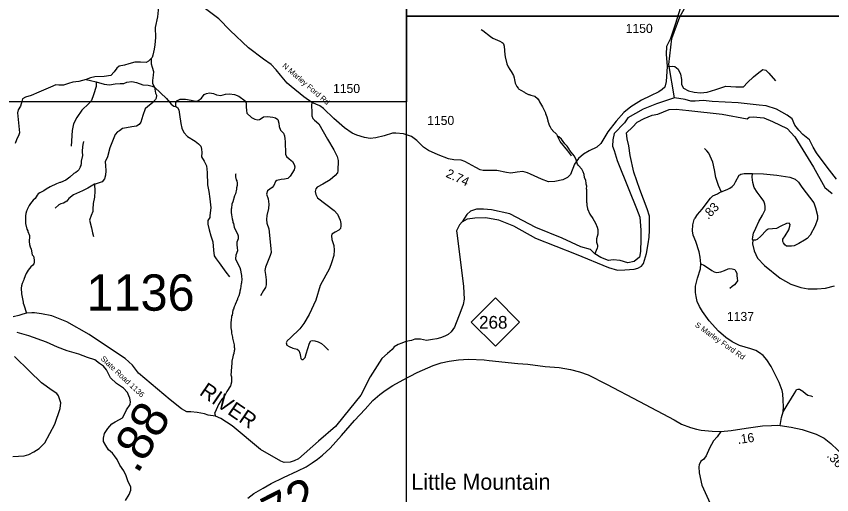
# Model space of a CAD drawing. Extents: x 1248089 to 1457196, y 820910 to 988753.
# Drawn here: x 1307656 to 1318874, y 862255 to 868837 of the extents above; entities that cross this region are included whole.
import ezdxf

# ---------------------------------------------------------------- set-up
doc = ezdxf.new("R2010")
doc.units = 0
for name, color, linetype in [('Exist Geographical Mountain Summit Label', 7, 'Continuous'), ('Exist Hydrographic Misc Water Feature', 7, 'Continuous'), ('Exist Hydrographic River Shore', 7, 'Continuous'), ('Exist Hydrographic River Shore Label', 7, 'Continuous'), ('Exist Road Non-System Type 51', 7, 'Continuous'), ('Exist Road Primary NC Attributed', 7, 'Continuous'), ('Exist Road Primary NC Shield CELL', 7, 'Continuous'), ('Exist Road Primary NC Shield Number Label', 7, 'Continuous'), ('Exist Road Secondary Type 20 Attributed', 7, 'Continuous'), ('Exist Road Secondary Type 41 Attributed', 7, 'Continuous'), ('Exist Road Secondary Type 51 Attributed', 7, 'Continuous'), ('Exist Road Secondary Type 51 Label', 7, 'Continuous'), ('Map Preparation Inset Cut Line', 7, 'Continuous'), ('Prop CMT Slope Fill', 7, 'Continuous'), ('Prop GRAU CAT1 Cell', 7, 'Continuous'), ('Prop Lane Lines', 7, 'Continuous')]:
    doc.layers.add(name, color=color, linetype=linetype)

msp = doc.modelspace()

# ---------------------------------------------------------------- linework, layer by layer
at = {"layer": 'Exist Hydrographic Misc Water Feature'}
for points in [[(1316710, 867717), (1316635, 868174), (1316677, 868531), (1316783, 868831), (1316869, 868977), (1317023, 869141), (1317228, 869295), (1317348, 869460), (1317428, 869642), (1317574, 869836), (1318042, 870227), (1318137, 870383), (1318167, 870599), (1318127, 870665), (1317873, 870838), (1317082, 871258), (1316656, 871617)], [(1314053, 868653), (1314075, 868640), (1314179, 868558), (1314210, 868537), (1314309, 868493), (1314341, 868476), (1314353, 868466), (1314358, 868458), (1314368, 868426), (1314374, 868365), (1314374, 868341), (1314378, 868333), (1314377, 868301), (1314381, 868293), (1314380, 868277), (1314406, 868181), (1314423, 868140), (1314445, 868106), (1314466, 868079), (1314495, 868023), (1314506, 867990), (1314509, 867962), (1314520, 867918), (1314543, 867869), (1314559, 867847), (1314567, 867841), (1314598, 867820), (1314646, 867795), (1314657, 867785), (1314711, 867756), (1314717, 867761), (1314733, 867753), (1314790, 867738), (1314826, 867707), (1314849, 867674), (1314854, 867660), (1314897, 867589), (1314935, 867508), (1314935, 867500), (1314954, 867452), (1314969, 867404), (1314969, 867396), (1314984, 867355), (1314983, 867347), (1314999, 867315), (1315014, 867288), (1315032, 867270), (1315034, 867264), (1315088, 867213), (1315103, 867189)], [(1315236, 867052), (1315225, 867060), (1315201, 867081), (1315155, 867148), (1315122, 867180), (1315103, 867189)], [(1315295, 866914), (1315286, 866931), (1315242, 866988), (1315140, 867112), (1315110, 867168), (1315103, 867189)], [(1308582, 867113), (1308573, 867073), (1308572, 867058), (1308568, 867050), (1308564, 866970), (1308565, 866922), (1308551, 866842), (1308551, 866818), (1308542, 866786), (1308534, 866770), (1308534, 866762), (1308515, 866725), (1308500, 866707), (1308476, 866688), (1308450, 866672), (1308394, 866624), (1308338, 866583), (1308265, 866549), (1308257, 866549), (1308210, 866532), (1308121, 866490), (1308065, 866458), (1308036, 866436), (1307982, 866407), (1307959, 866392), (1307945, 866376), (1307914, 866329), (1307889, 866306), (1307850, 866259), (1307834, 866235), (1307804, 866180), (1307804, 866172), (1307796, 866156), (1307787, 866124), (1307782, 866092), (1307781, 866012), (1307784, 866004), (1307784, 865988), (1307802, 865908), (1307814, 865883), (1307814, 865875), (1307836, 865819), (1307834, 865723), (1307838, 865715), (1307838, 865699), (1307845, 865667), (1307860, 865634), (1307874, 865554), (1307894, 865536)], [(1315506, 866270), (1315504, 866295), (1315507, 866447), (1315503, 866461), (1315504, 866499), (1315497, 866527), (1315497, 866543), (1315490, 866579), (1315475, 866620), (1315468, 866660), (1315457, 866696), (1315436, 866733), (1315389, 866786), (1315379, 866802), (1315355, 866875), (1315330, 866915), (1315273, 866989), (1315262, 867009), (1315236, 867052)], [(1310676, 866668), (1310672, 866660), (1310671, 866628), (1310682, 866588), (1310689, 866572), (1310697, 866540), (1310696, 866508), (1310687, 866476), (1310687, 866460), (1310670, 866396), (1310657, 866365), (1310635, 866285), (1310622, 866254), (1310617, 866198), (1310613, 866182), (1310611, 866126), (1310615, 866118), (1310615, 866104), (1310626, 866050), (1310637, 866017), (1310637, 866001), (1310644, 865985), (1310655, 865937), (1310705, 865832), (1310708, 865816), (1310708, 865776), (1310690, 865728), (1310689, 865688), (1310697, 865656), (1310700, 865612), (1310678, 865548), (1310673, 865501), (1310677, 865484), (1310731, 865379), (1310742, 865347), (1310752, 865287), (1310756, 865279), (1310756, 865247), (1310759, 865230), (1310754, 865167), (1310750, 865159), (1310740, 865087), (1310731, 865055), (1310731, 865039), (1310718, 864992), (1310701, 864952), (1310701, 864944), (1310667, 864873), (1310667, 864865), (1310654, 864841), (1310646, 864809), (1310637, 864793), (1310629, 864762), (1310624, 864722), (1310619, 864714), (1310614, 864642), (1310610, 864634), (1310608, 864554), (1310611, 864522), (1310615, 864514), (1310618, 864478), (1310633, 864422), (1310632, 864406), (1310655, 864317), (1310654, 864285), (1310657, 864269), (1310657, 864245), (1310653, 864237), (1310648, 864197), (1310639, 864174), (1310637, 864153)], [(1315506, 866270), (1315506, 866227), (1315510, 866219), (1315513, 866187), (1315548, 866114), (1315586, 866057), (1315625, 865992), (1315648, 865936), (1315655, 865904), (1315657, 865840), (1315640, 865776), (1315639, 865728), (1315650, 865688), (1315651, 865664), (1315649, 865648), (1315636, 865616), (1315617, 865569)], [(1307894, 865536), (1307901, 865485), (1307904, 865469), (1307904, 865445), (1307897, 865430), (1307885, 865414), (1307858, 865388), (1307821, 865343), (1307794, 865296), (1307778, 865264), (1307759, 865217), (1307758, 865209), (1307746, 865185), (1307746, 865177), (1307737, 865161), (1307729, 865130), (1307724, 865098), (1307726, 865018), (1307751, 864905), (1307751, 864889), (1307759, 864865), (1307798, 864754)], [(1310637, 864153), (1310621, 864090), (1310615, 863986), (1310611, 863978), (1310612, 863946), (1310609, 863906), (1310616, 863874), (1310618, 863842), (1310615, 863802), (1310602, 863754), (1310554, 863676), (1310531, 863628), (1310510, 863597), (1310486, 863567), (1310440, 863494), (1310390, 863391), (1310385, 863376), (1310397, 863337)]]:
    msp.add_lwpolyline(points, dxfattribs=at)
at = {"layer": 'Exist Hydrographic River Shore'}
for points in [[(1318941, 866595), (1318811, 866759), (1318664, 866958), (1318617, 867035), (1318570, 867135), (1318475, 867212), (1318423, 867268), (1318367, 867338), (1318332, 867424), (1318263, 867476), (1318117, 867558), (1317974, 867605), (1317875, 867614), (1317711, 867631), (1317586, 867648), (1317228, 867666), (1317107, 867679), (1316995, 867670), (1316934, 867670), (1316857, 867692), (1316710, 867717), (1316464, 867631)], [(1316464, 867631), (1316279, 867558), (1316069, 867438), (1316023, 867371), (1315880, 867222), (1315863, 867138), (1315860, 867052), (1315883, 866989), (1315923, 866852), (1316083, 866453), (1316189, 866193), (1316236, 866072), (1316249, 865892), (1316249, 865769), (1316242, 865599), (1316229, 865522), (1316156, 865463), (1316069, 865446), (1315966, 865479), (1315866, 865486), (1315803, 865476), (1315700, 865516), (1315617, 865569), (1315554, 865629), (1315424, 865666), (1315168, 865782), (1314805, 865932), (1314448, 866118), (1314196, 866174), (1314082, 866181), (1313989, 866184), (1313903, 866154), (1313856, 866111), (1313790, 866011)], [(1313790, 866011), (1313863, 866048), (1313963, 866065), (1314116, 866068), (1314289, 866035), (1314498, 865955), (1314801, 865782), (1315360, 865565), (1315804, 865380), (1315927, 865344), (1316030, 865347), (1316156, 865357), (1316206, 865370), (1316256, 865400), (1316283, 865437), (1316326, 865573), (1316349, 865707), (1316363, 865800), (1316369, 865896), (1316366, 866089), (1316336, 866186), (1316233, 866455), (1316153, 866690), (1316103, 866923), (1316083, 867056), (1316060, 867152), (1316050, 867232), (1316133, 867312), (1316200, 867382), (1316293, 867432), (1316406, 867475), (1316482, 867491)], [(1316482, 867491), (1316637, 867553), (1316736, 867558), (1316908, 867540), (1317366, 867489), (1317711, 867428), (1317737, 867450), (1317793, 867454), (1317940, 867441), (1318060, 867389), (1318263, 867294), (1318367, 867178), (1318626, 866759), (1318781, 866483), (1318880, 866401)], [(1313790, 866011), (1313753, 865969), (1313713, 865886), (1313723, 865823), (1313810, 865117), (1313820, 864947), (1313803, 864871), (1313770, 864784), (1313684, 864560), (1313640, 864494), (1313597, 864461), (1313554, 864434), (1313491, 864414), (1313441, 864401), (1313381, 864391), (1313325, 864381), (1313301, 864377), (1313215, 864394), (1313138, 864394), (1313095, 864377), (1313015, 864361), (1312962, 864341), (1312909, 864321), (1312856, 864291), (1312826, 864254), (1312762, 864198), (1312686, 864128), (1312526, 863875), (1312398, 863623), (1312162, 863337), (1312049, 863194), (1311812, 862991), (1311537, 862748), (1311480, 862722), (1311424, 862702), (1311341, 862699), (1311294, 862715), (1311018, 862875), (1310626, 863201), (1310470, 863304), (1310397, 863337), (1310297, 863350), (1310247, 863367), (1310144, 863384), (1310058, 863394), (1310001, 863397), (1309931, 863434), (1309772, 863560), (1309337, 863926), (1309257, 864039), (1309154, 864129), (1308925, 864282), (1308659, 864458), (1308350, 864631), (1308144, 864717), (1308001, 864744), (1307908, 864757), (1307868, 864757), (1307798, 864754), (1307748, 864737), (1307689, 864721), (1307612, 864701)], [(1307610, 862778), (1307764, 862788), (1307829, 862808), (1307899, 862843), (1307969, 862888), (1308049, 862968), (1308187, 863225), (1308262, 863439), (1308267, 863519), (1308252, 863574), (1308237, 863614), (1308212, 863649), (1308152, 863689), (1308002, 863794), (1307838, 863954), (1307633, 864158)]]:
    msp.add_lwpolyline(points, dxfattribs=at)
at = {"layer": 'Exist Road Non-System Type 51'}
for points in [[(1309654, 869486), (1309633, 869416), (1309603, 869340), (1309599, 869292), (1309607, 869212), (1309613, 869138), (1309609, 869072), (1309599, 868988), (1309607, 868922), (1309601, 868830), (1309569, 868682), (1309571, 868546), (1309561, 868445), (1309555, 868383), (1309537, 868301), (1309525, 868271), (1309515, 868259)], [(1309515, 868259), (1309475, 868219), (1309443, 868199), (1309367, 868207), (1309289, 868205), (1309203, 868183), (1309145, 868163), (1309073, 868151), (1309041, 868122), (1309005, 868072), (1308957, 868022), (1308867, 868010), (1308737, 868002), (1308677, 867992), (1308617, 867966)], [(1309558, 867860), (1309536, 867910), (1309536, 867954), (1309546, 868028), (1309548, 868072), (1309528, 868132), (1309518, 868178), (1309515, 868259)], [(1316609, 868148), (1316682, 868151), (1316715, 868144), (1316762, 868108), (1316794, 868039), (1316809, 867966), (1316809, 867897), (1316834, 867846), (1316903, 867813), (1316980, 867791), (1317071, 867784), (1317161, 867791), (1317278, 867831), (1317416, 867875), (1317554, 867868), (1317659, 867868), (1317717, 867926), (1317797, 868006), (1317870, 868064), (1317928, 868104), (1317968, 868097), (1318011, 868053), (1318099, 867951)], [(1308617, 867966), (1308518, 867941), (1308432, 867929), (1308376, 867911), (1308308, 867889), (1308242, 867889), (1308198, 867893), (1308128, 867863), (1307968, 867795), (1307860, 867749), (1307782, 867723), (1307742, 867703), (1307732, 867665), (1307714, 867599), (1307680, 867551), (1307674, 867507), (1307682, 867415), (1307699, 867232), (1307691, 867204), (1307657, 867136), (1307643, 867088)], [(1308757, 867936), (1308756, 867872), (1308720, 867754), (1308690, 867676), (1308656, 867635), (1308556, 867543), (1308490, 867443), (1308444, 867355), (1308424, 867265), (1308412, 867048)], [(1308617, 867966), (1308675, 867952), (1308757, 867936)], [(1308757, 867936), (1308864, 867904), (1308940, 867892), (1309018, 867908), (1309084, 867914), (1309138, 867912), (1309176, 867932), (1309246, 867940), (1309312, 867924), (1309396, 867896), (1309470, 867890), (1309526, 867876), (1309558, 867860)], [(1309558, 867860), (1309573, 867780), (1309583, 867750), (1309581, 867712), (1309571, 867692), (1309529, 867648), (1309465, 867598), (1309431, 867562), (1309397, 867472), (1309369, 867380), (1309347, 867350), (1309309, 867327), (1309245, 867315), (1309173, 867303), (1309119, 867291), (1309075, 867263), (1309047, 867247), (1309017, 867211), (1308943, 867027), (1308910, 866902), (1308880, 866836), (1308884, 866784), (1308888, 866710), (1308884, 866650), (1308870, 866600), (1308838, 866558), (1308782, 866540), (1308742, 866528), (1308730, 866526), (1308738, 866429), (1308734, 866349), (1308712, 866263), (1308708, 866183), (1308708, 866153), (1308686, 866094), (1308664, 866034), (1308692, 865928), (1308704, 865856), (1308718, 865809)], [(1309558, 867860), (1309723, 867708), (1309785, 867628), (1309823, 867602), (1309853, 867596)], [(1309853, 867596), (1309851, 867625), (1309853, 867649), (1309875, 867677), (1309913, 867695), (1309985, 867695), (1310063, 867681), (1310123, 867671), (1310155, 867673), (1310203, 867709), (1310243, 867759), (1310275, 867775), (1310315, 867785), (1310369, 867773), (1310409, 867757), (1310471, 867749), (1310535, 867765), (1310591, 867771), (1310657, 867763), (1310717, 867739), (1310805, 867673), (1310821, 867643), (1310820, 867592), (1310824, 867542), (1310830, 867506), (1310890, 867445), (1310936, 867421), (1310980, 867413), (1311004, 867417), (1311038, 867441), (1311058, 867453), (1311114, 867459), (1311184, 867451), (1311222, 867439), (1311254, 867417), (1311266, 867368), (1311272, 867320), (1311290, 867268), (1311332, 867228), (1311344, 867192), (1311350, 867150), (1311356, 867114), (1311358, 866942), (1311372, 866910), (1311410, 866876), (1311458, 866840), (1311478, 866798), (1311486, 866764), (1311480, 866726), (1311424, 866636), (1311390, 866606), (1311348, 866596), (1311302, 866592), (1311242, 866578), (1311224, 866562), (1311200, 866509), (1311178, 866480), (1311114, 866436), (1311098, 866390), (1311122, 866324), (1311132, 866252), (1311124, 866192), (1311104, 866098), (1311098, 866040), (1311104, 865992), (1311132, 865912), (1311158, 865644), (1311164, 865588), (1311150, 865545), (1311084, 865385), (1311076, 865339), (1311086, 865285), (1311092, 865211), (1311092, 865141), (1311084, 865107), (1311058, 865065), (1311016, 864993)], [(1309853, 867596), (1309873, 867582), (1309893, 867548), (1309903, 867486), (1309919, 867363), (1309933, 867299), (1309961, 867239), (1310013, 867181), (1310117, 867119), (1310165, 867081), (1310193, 867049), (1310203, 867009), (1310209, 866965), (1310203, 866903), (1310243, 866845), (1310273, 866779), (1310283, 866687), (1310285, 866519), (1310305, 866424), (1310321, 866324), (1310333, 866200), (1310321, 866096), (1310317, 866070), (1310293, 866028), (1310291, 865975), (1310311, 865899), (1310333, 865817), (1310359, 865733), (1310371, 865617), (1310379, 865539), (1310407, 865499), (1310449, 865443), (1310541, 865317), (1310589, 865251)], [(1311722, 867653), (1311718, 867608), (1311720, 867516), (1311722, 867466), (1311736, 867430), (1311760, 867408), (1311820, 867358), (1311938, 867148), (1312026, 867001)], [(1317359, 866417), (1317319, 866511), (1317281, 866621), (1317263, 866723), (1317241, 866829), (1317183, 866953), (1317155, 866985), (1317141, 867001), (1317123, 867017)], [(1312026, 867001), (1312072, 866909), (1312084, 866851), (1312082, 866709), (1312077, 866683), (1312043, 866647), (1311973, 866587), (1311875, 866527), (1311797, 866485), (1311777, 866461), (1311769, 866425), (1311777, 866385), (1311801, 866338), (1312031, 866164), (1312077, 866114), (1312111, 866034), (1312123, 865984), (1312123, 865954), (1312115, 865918), (1312095, 865896), (1312041, 865866), (1311997, 865839), (1311991, 865815), (1311999, 865765), (1312023, 865683), (1312031, 865617), (1312027, 865545), (1311991, 865443), (1311965, 865368), (1311835, 865133), (1311775, 864933), (1311687, 864734), (1311613, 864612), (1311555, 864536), (1311429, 864414), (1311381, 864372), (1311371, 864342), (1311379, 864312), (1311409, 864294), (1311461, 864270), (1311521, 864256), (1311543, 864238), (1311557, 864204), (1311565, 864155), (1311569, 864127), (1311583, 864115), (1311601, 864113), (1311631, 864143), (1311645, 864195), (1311691, 864341), (1311707, 864371), (1311729, 864375), (1311763, 864371), (1311811, 864357), (1311853, 864337), (1311897, 864299), (1311951, 864243)], [(1317668, 866673), (1317783, 866676), (1317938, 866668), (1318118, 866652), (1318296, 866625), (1318372, 866594), (1318418, 866554), (1318463, 866485), (1318629, 866270), (1318651, 866203), (1318680, 866095), (1318680, 866046), (1318647, 865955), (1318576, 865826), (1318538, 865779), (1318500, 865755), (1318420, 865710), (1318358, 865679), (1318321, 865673), (1318252, 865675), (1318228, 865693), (1318212, 865721), (1318203, 865740), (1318203, 865770), (1318234, 865817), (1318285, 865899), (1318298, 865948), (1318301, 865970), (1318287, 865990), (1318252, 865988), (1318176, 865950), (1318114, 865915), (1318061, 865912), (1317999, 865910), (1317972, 865888), (1317899, 865810), (1317848, 865764), (1317828, 865757), (1317790, 865755), (1317786, 865768), (1317791, 865804), (1317798, 865852)], [(1317798, 865852), (1317830, 865924), (1317870, 866014), (1317920, 866100), (1317958, 866174), (1317958, 866220), (1317952, 866254), (1317940, 866292), (1317904, 866344), (1317848, 866418), (1317808, 866482), (1317788, 866550), (1317778, 866624), (1317783, 866676)], [(1308730, 866526), (1308642, 866474), (1308568, 866434), (1308442, 866382), (1308380, 866330), (1308352, 866292), (1308306, 866268), (1308268, 866256), (1308240, 866242), (1308192, 866198)], [(1317790, 865755), (1317785, 865707), (1317806, 865610), (1317853, 865511), (1317949, 865406), (1318163, 865234), (1318312, 865150), (1318450, 865106), (1318550, 865085), (1318675, 865085), (1318787, 865095), (1318915, 865129)], [(1317072, 865431), (1317115, 865412), (1317152, 865389), (1317227, 865337), (1317258, 865319), (1317295, 865310), (1317347, 865319), (1317399, 865339), (1317449, 865364), (1317469, 865366), (1317505, 865360), (1317540, 865352), (1317552, 865333), (1317567, 865302), (1317571, 865267), (1317575, 865236), (1317577, 865198), (1317556, 865167), (1317536, 865144), (1317507, 865121), (1317473, 865092)], [(1318208, 863394), (1318261, 863487), (1318321, 863585), (1318360, 863643), (1318379, 863678), (1318392, 863700), (1318409, 863708), (1318433, 863705), (1318477, 863681), (1318512, 863645), (1318548, 863626), (1318586, 863615), (1318610, 863607)]]:
    msp.add_lwpolyline(points, dxfattribs=at)
at = {"layer": 'Exist Road Primary NC Attributed'}
for points in [[(1310841, 862208), (1310923, 862270), (1311051, 862345), (1311162, 862410), (1311331, 862492), (1311530, 862581), (1311643, 862638), (1311727, 862691), (1311800, 862744), (1311871, 862798), (1311973, 862895), (1312129, 863071), (1312310, 863276), (1312454, 863432), (1312563, 863552), (1312659, 863634), (1312729, 863689), (1312838, 863757), (1312978, 863835), (1313173, 863935), (1313390, 864033), (1313503, 864068), (1313612, 864090), (1313740, 864110), (1313876, 864119), (1314093, 864108), (1314164, 864099), (1314554, 864059), (1314692, 864050), (1314931, 864019), (1315127, 864006), (1315281, 863977), (1315403, 863946), (1315523, 863904), (1315776, 863777), (1316228, 863538), (1316705, 863285), (1316808, 863227), (1316930, 863181), (1317013, 863154), (1317077, 863141), (1317230, 863130), (1317348, 863126)], [(1317348, 863126), (1317491, 863140), (1317699, 863170), (1317923, 863202), (1318047, 863208), (1318133, 863209), (1318163, 863206)], [(1318163, 863206), (1318317, 863185), (1318469, 863152), (1318659, 863089), (1318771, 863031), (1318864, 862958), (1318960, 862869), (1319100, 862716), (1319209, 862609), (1319323, 862531), (1319448, 862455), (1319619, 862390), (1319711, 862368), (1319796, 862354)]]:
    msp.add_lwpolyline(points, dxfattribs=at)
at = {"layer": 'Exist Road Primary NC Shield CELL'}
msp.add_lwpolyline([(1313914, 864629), (1314247, 864962), (1314580, 864629), (1314247, 864296)], close=True, dxfattribs=at)
at = {"layer": 'Exist Road Secondary Type 20 Attributed'}
msp.add_lwpolyline([(1309159, 862174), (1309208, 862257), (1309234, 862318), (1309234, 862360), (1309190, 862445), (1309168, 862513), (1309138, 862585), (1309081, 862662), (1309042, 862739), (1309007, 862791), (1308978, 862828), (1308923, 862870), (1308886, 862933), (1308858, 862986), (1308854, 863034), (1308869, 863097), (1308915, 863167), (1308969, 863229), (1309015, 863255), (1309074, 863288), (1309118, 863310), (1309138, 863346), (1309173, 863420), (1309223, 863495), (1309229, 863532), (1309218, 863582), (1309205, 863615), (1309188, 863663), (1309129, 863720), (1309033, 863786), (1308954, 863862), (1308897, 863974), (1308856, 864021), (1308801, 864060), (1308738, 864110), (1308635, 864143), (1308517, 864189), (1308358, 864233), (1308222, 864283), (1308074, 864351), (1307829, 864439), (1307670, 864486)], dxfattribs=at)
at = {"layer": 'Exist Road Secondary Type 41 Attributed'}
msp.add_lwpolyline([(1316812, 869019), (1316725, 868740), (1316656, 868533), (1316602, 868420), (1316598, 868315), (1316609, 868148), (1316598, 867940), (1316580, 867860), (1316544, 867831), (1316498, 867798), (1316381, 867742), (1316256, 867682), (1316109, 867591), (1316015, 867515), (1315909, 867393), (1315794, 867247), (1315727, 867132), (1315700, 867086), (1315641, 867038), (1315537, 866988), (1315460, 866942), (1315389, 866881), (1315336, 866803), (1315279, 866662), (1315241, 866618), (1315175, 866586), (1315066, 866565), (1314980, 866560), (1314882, 866598), (1314732, 866667), (1314689, 866685), (1314623, 866700), (1314547, 866693), (1314458, 866680), (1314401, 866688), (1314269, 866715), (1314176, 866717), (1314079, 866717), (1314038, 866726), (1313977, 866756), (1313825, 866837), (1313778, 866856), (1313678, 866864), (1313603, 866876), (1313460, 866932), (1313328, 866990), (1313258, 867037), (1313167, 867130), (1313093, 867184), (1312984, 867219), (1312877, 867229), (1312830, 867230), (1312715, 867192), (1312601, 867164), (1312525, 867156), (1312446, 867171), (1312341, 867201), (1312276, 867230), (1312170, 867304), (1312025, 867429), (1311884, 867566), (1311832, 867604), (1311722, 867653), (1311610, 867731), (1311440, 867869), (1311382, 867916), (1311291, 868029), (1311231, 868098), (1311162, 868174), (1311059, 868248), (1310853, 868402), (1310600, 868643), (1310442, 868803), (1310015, 869126)], dxfattribs=at)
at = {"layer": 'Exist Road Secondary Type 51 Attributed'}
for points in [[(1318163, 863206), (1318185, 863318), (1318208, 863394), (1318210, 863463), (1318208, 863556), (1318201, 863643), (1318192, 863689), (1318150, 863798), (1318041, 864020), (1317984, 864112), (1317933, 864170), (1317880, 864208), (1317829, 864237), (1317762, 864263), (1317604, 864308), (1317505, 864359), (1317420, 864417), (1317316, 864505), (1317187, 864645), (1317095, 864773), (1317055, 864842), (1317024, 864915), (1317008, 864980), (1316999, 865035), (1317002, 865126), (1317029, 865233), (1317070, 865362), (1317072, 865431), (1317064, 865525), (1317053, 865596), (1317004, 865738), (1316970, 865827), (1316959, 865887), (1316966, 865969), (1316983, 866039), (1316987, 866051), (1316994, 866060), (1317028, 866108), (1317090, 866184), (1317209, 866335), (1317240, 866365), (1317270, 866382), (1317301, 866396), (1317332, 866413), (1317355, 866423), (1317435, 866454), (1317471, 866474), (1317505, 866496), (1317531, 866524), (1317553, 866558), (1317603, 866650), (1317610, 866657), (1317623, 866666), (1317668, 866673)], [(1317348, 863126), (1317300, 863051), (1317248, 862994), (1317195, 862896), (1317146, 862789), (1317111, 862740), (1317073, 862714), (1317053, 862667), (1317044, 862636), (1317051, 862556), (1317089, 862385), (1317202, 862133)]]:
    msp.add_lwpolyline(points, dxfattribs=at)
at = {"layer": 'Map Preparation Inset Cut Line'}
for points in [[(1313026, 913085), (1388709, 913085), (1388709, 884380), (1373501, 884377), (1373501, 868837), (1313026, 868837)], [(1313026, 867658), (1300767, 867658), (1300767, 889680), (1313026, 889680)], [(1313026, 824588), (1313026, 868837), (1388709, 868837), (1388709, 835631), (1373501, 835631), (1373501, 824588)]]:
    msp.add_lwpolyline(points, close=True, dxfattribs=at)

# ---------------------------------------------------------------- texts
at = {"layer": 'Exist Geographical Mountain Summit Label'}
msp.add_text('Little Mountain', height=220, dxfattribs=at).set_placement((1313092, 862322))
at = {"layer": 'Exist Hydrographic River Shore Label'}
msp.add_text('RIVER', height=210, rotation=325.6106, dxfattribs=at).set_placement((1310163, 863638))
at = {"layer": 'Exist Road Primary NC Shield Number Label'}
msp.add_text('268', height=175, dxfattribs=at).set_placement((1314023, 864539))
at = {"layer": 'Exist Road Secondary Type 51 Label'}
for s, rotation, p in [('N Marley Ford Rd', 319.2748, (1311310, 868145)), ('S Marley Ford Rd', 324.7299, (1316987, 864575)), ('State Road 1136', 316.8702, (1308810, 864119))]:
    msp.add_text(s, height=75, rotation=rotation, dxfattribs=at).set_placement(p)
at = {"layer": 'Prop CMT Slope Fill'}
for s, height, rotation, p in [('.16', 125, 8.1365, (1317586, 862951)), ('.36', 125, 312.565, (1318800, 862784)), ('1.72', 500, 27.102, (1310707, 861477))]:
    msp.add_text(s, height=height, rotation=rotation, dxfattribs=at).set_placement(p)
at = {"layer": 'Prop GRAU CAT1 Cell'}
for s, height, rotation, p in [('2.74', 125, 335.2082, (1313556, 866631)), ('.83', 125, 46.2414, (1317175, 866035)), ('.88', 500, 59.5091, (1309324, 862529))]:
    msp.add_text(s, height=height, rotation=rotation, dxfattribs=at).set_placement(p)
at = {"layer": 'Prop Lane Lines'}
for s, height, p in [('1150', 125, (1316040, 868608)), ('1150', 125, (1312014, 867781)), ('1150', 125, (1313309, 867341)), ('1136', 500, (1308622, 864786)), ('1137', 125, (1317433, 864644))]:
    msp.add_text(s, height=height, dxfattribs=at).set_placement(p)

doc.saveas('drawing.dxf')
